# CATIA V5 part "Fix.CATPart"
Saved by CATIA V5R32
Part number: Part1
Bounding box of the stored display mesh (mm): x -20 to 0, y -45 to 45, z -45 to 45
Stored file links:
  D:\PROJECTS\Project 2022\CATIA V5 6R 2022\Resources\Part Files\c16_catia_v5_6r2022_prt\Cable Joint - (Fig16-60)\Fix.CATPart
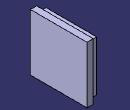
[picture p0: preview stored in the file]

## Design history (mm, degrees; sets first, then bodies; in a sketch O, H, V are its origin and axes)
Body1 (main body)
  Sketch1 on yz-plane, origin (0, 0, 0), H (0, 1, 0), V (0, 0, 1)
    line L1 (40, 40) -> (40, -40)
    line L2 (40, -40) -> (-40, -40)
    line L3 (-40, -40) -> (-40, 40)
    line L4 (-40, 40) -> (40, 40)
    line L5 (45, 45) -> (45, -45)
    line L6 (45, -45) -> (-45, -45)
    line L7 (-45, -45) -> (-45, 45)
    line L8 (-45, 45) -> (45, 45)
    length L4 = 80
    length L1 = 80
    length L5 = 90
    length L8 = 90
    vertical: L1 V, L3 V, L5 V, L7 V
    horizontal: L2 H, L4 H, L6 H, L8 H
    equidistance: L1 L3 O, L2 L4 O, L5 L7 O, L6 L8 O
  MultiPad1: profile Sketch1, domains (length 10; length 20)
